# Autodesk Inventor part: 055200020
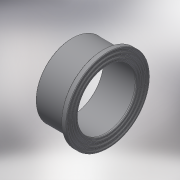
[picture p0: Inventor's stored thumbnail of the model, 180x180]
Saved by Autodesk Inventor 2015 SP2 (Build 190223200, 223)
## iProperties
Created: 2017-10
Part Number: 055200020
Material: Generic
Description: PLASSON FLANGE(FLAT GASKET)C 20
Document SubType Name: Modeling
Designer: KIM
Density: 1 g/cm^3
Appearance: Default
Author: KIM
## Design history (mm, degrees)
derived "055200.ipt"
feature "Solid1::055200.ipt"
tag "TaggingFeature1"
body "Solid1"
other parameters: "d0" = 19, "d1" = 27, "d3" = 19, "d4" = 7, "d5" = 16, "d6" = 34, "d8" = 2.1, "d11" = 0.2, "d12" = 1.05, "E_" = 27, "E_1" = 34, "l_" = 16, "B_" = 7, "H_" = 19, "d14" = 7.5
